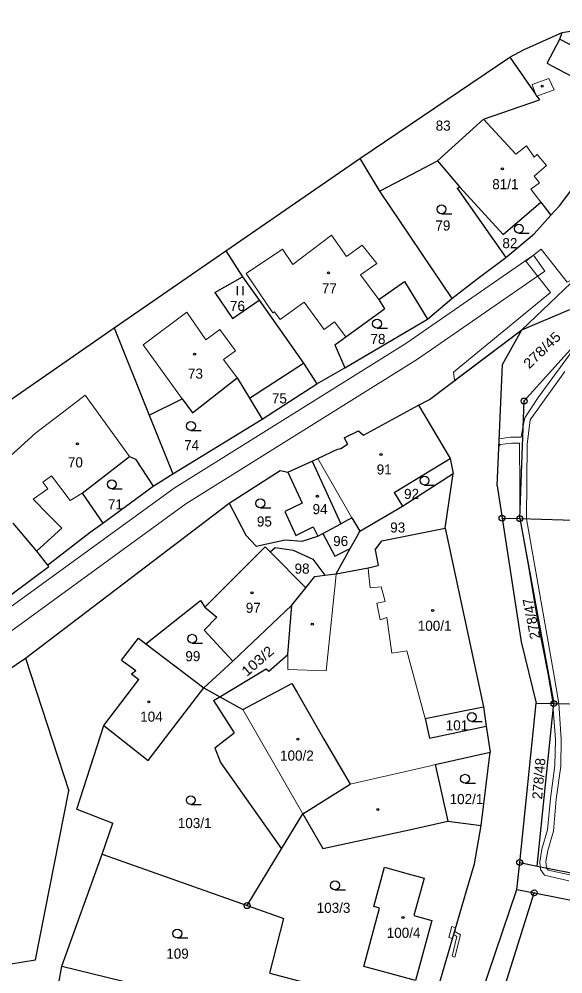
# Model space of a CAD drawing. Extents: x -633485 to -630509, y -1112692 to -1108818.
# Drawn here: x -631835.2 to -631743.5, y -1111718.1 to -1111557 of the extents above; entities that cross this region are included whole.
import ezdxf
from ezdxf.enums import TextEntityAlignment as Align

# ---------------------------------------------------------------- set-up
doc = ezdxf.new("R2010")
doc.units = 0
doc.header["$LTSCALE"] = 0.68
for name, color, linetype, lineweight in [('1', 7, 'Continuous', 25), ('13', 7, 'Continuous', 13), ('3', 7, 'Continuous', 25), ('4', 7, 'Continuous', 13), ('5', 7, 'Continuous', 25), ('8', 7, 'Continuous', 25)]:
    doc.layers.add(name, color=color, linetype=linetype, lineweight=lineweight)
doc.layers.add('2', color=7, linetype='Continuous')

msp = doc.modelspace()

# ---------------------------------------------------------------- linework, layer by layer
at = {"layer": '1'}
for p, q in [((-631743.57, -1111559.29), (-631729.66, -1111557.04)), ((-631750.09, -1111562.23), (-631743.57, -1111559.29)), ((-631743.97, -1111560.4), (-631743.57, -1111559.29)), ((-631746.12, -1111564.5), (-631743.97, -1111560.4)), ((-631743.97, -1111560.4), (-631737.55, -1111563.79)), ((-631752.41, -1111563.48), (-631750.09, -1111562.23)), ((-631777.7, -1111580.55), (-631752.41, -1111563.48)), ((-631752.41, -1111563.48), (-631748.06, -1111569.69)), ((-631746.12, -1111564.5), (-631745.34, -1111564.91)), ((-631745.34, -1111564.91), (-631739.54, -1111567.99)), ((-631748.06, -1111569.69), (-631747.93, -1111570.05)), ((-631747.93, -1111570.05), (-631747.83, -1111570.01)), ((-631747.83, -1111570.01), (-631747.38, -1111570.66)), ((-631756.86, -1111573.91), (-631747.38, -1111570.66)), ((-631764.62, -1111580.92), (-631756.86, -1111573.91)), ((-631800.32, -1111596.13), (-631777.7, -1111580.55)), ((-631777.7, -1111580.55), (-631774.39, -1111586.04)), ((-631769.01, -1111583.27), (-631764.62, -1111580.92)), ((-631764.62, -1111580.92), (-631760.86, -1111585.37)), ((-631774.39, -1111586.04), (-631769.01, -1111583.27)), ((-631774.39, -1111586.04), (-631762.2, -1111604.18)), ((-631761.3, -1111585.56), (-631760.86, -1111585.37)), ((-631761.3, -1111585.56), (-631753.08, -1111597.25)), ((-631760.86, -1111585.37), (-631753.55, -1111593.39)), ((-631744.02, -1111588.52), (-631741.6, -1111585.3)), ((-631753.55, -1111593.39), (-631747.16, -1111587.9)), ((-631747.16, -1111587.9), (-631745.47, -1111590.11)), ((-631750.36, -1111609.45), (-631728.81, -1111588.83)), ((-631745.47, -1111590.11), (-631744.02, -1111588.52)), ((-631748.32, -1111593.26), (-631745.47, -1111590.11)), ((-631753.08, -1111597.25), (-631748.32, -1111593.26)), ((-631819.16, -1111609.13), (-631800.32, -1111596.13)), ((-631800.32, -1111596.13), (-631797.47, -1111600.51)), ((-631758, -1111600.91), (-631753.08, -1111597.25)), ((-631802.15, -1111603.12), (-631797.47, -1111600.51)), ((-631797.47, -1111600.51), (-631794.69, -1111604.45)), ((-631762.2, -1111604.18), (-631758, -1111600.91)), ((-631774.51, -1111604.35), (-631770.17, -1111601.27)), ((-631770.17, -1111601.27), (-631766.3, -1111607.62)), ((-631802.15, -1111603.12), (-631799.16, -1111607.53)), ((-631799.16, -1111607.53), (-631794.69, -1111604.45)), ((-631794.69, -1111604.45), (-631787.22, -1111615.07)), ((-631774.51, -1111604.35), (-631773.54, -1111605.89)), ((-631766.3, -1111607.62), (-631762.2, -1111604.18)), ((-631780.09, -1111610.64), (-631773.54, -1111605.89)), ((-631750.36, -1111609.45), (-631742.31, -1111606)), ((-631780.24, -1111615.86), (-631766.3, -1111607.62)), ((-631848.51, -1111629.48), (-631819.16, -1111609.13)), ((-631819.16, -1111609.13), (-631813.24, -1111623.81)), ((-631781.94, -1111611.99), (-631780.09, -1111610.64)), ((-631765.95, -1111621.17), (-631750.36, -1111609.45)), ((-631753.65, -1111615.31), (-631750.36, -1111609.45)), ((-631781.94, -1111611.99), (-631780.24, -1111615.86)), ((-631796.33, -1111620.95), (-631787.22, -1111615.07)), ((-631787.22, -1111615.07), (-631784.98, -1111618.54)), ((-631754.57, -1111635.74), (-631753.65, -1111615.31)), ((-631784.98, -1111618.54), (-631780.24, -1111615.86)), ((-631805.93, -1111623.44), (-631798.41, -1111617.54)), ((-631798.41, -1111617.54), (-631796.33, -1111620.95)), ((-631794.16, -1111624.52), (-631784.98, -1111618.54)), ((-631813.24, -1111623.81), (-631807.65, -1111621.07)), ((-631807.65, -1111621.07), (-631805.93, -1111623.44)), ((-631796.33, -1111620.95), (-631794.16, -1111624.52)), ((-631777.07, -1111627.2), (-631767.81, -1111622.12)), ((-631767.81, -1111622.12), (-631765.95, -1111621.17)), ((-631767.81, -1111622.12), (-631762.49, -1111631.16)), ((-631750.72, -1111641.28), (-631750, -1111621.44)), ((-631813.24, -1111623.81), (-631809.24, -1111633.72)), ((-631809.24, -1111633.72), (-631794.16, -1111624.52)), ((-631780.33, -1111627.68), (-631777.92, -1111626.46)), ((-631777.92, -1111626.46), (-631777.07, -1111627.2)), ((-631780.33, -1111627.68), (-631779.8, -1111628.75)), ((-631784.78, -1111631.16), (-631781.47, -1111629.58)), ((-631781.47, -1111629.58), (-631780.91, -1111629.46)), ((-631780.91, -1111629.46), (-631779.8, -1111628.75)), ((-631824.55, -1111637.01), (-631816.56, -1111630.81)), ((-631816.56, -1111630.81), (-631815.55, -1111631.24)), ((-631815.55, -1111631.24), (-631812.55, -1111635.79)), ((-631789.82, -1111633.44), (-631785.75, -1111631.57)), ((-631785.75, -1111631.57), (-631784.78, -1111631.16)), ((-631785.75, -1111631.57), (-631780.9, -1111642.13)), ((-631771.89, -1111636.87), (-631762.49, -1111631.16)), ((-631762.49, -1111631.16), (-631761.94, -1111633.69)), ((-631799.75, -1111638.66), (-631791.13, -1111633.15)), ((-631791.13, -1111633.15), (-631789.82, -1111633.44)), ((-631789.82, -1111633.44), (-631787.41, -1111638.68)), ((-631812.55, -1111635.79), (-631809.24, -1111633.72)), ((-631770.53, -1111639.18), (-631761.94, -1111633.69)), ((-631763.33, -1111642.86), (-631761.94, -1111633.69)), ((-631821.06, -1111642.04), (-631812.55, -1111635.79)), ((-631754.57, -1111635.74), (-631753.72, -1111641.2)), ((-631824.55, -1111637.01), (-631821.06, -1111642.04)), ((-631771.89, -1111636.87), (-631770.53, -1111639.18)), ((-631834.1, -1111664.82), (-631799.75, -1111638.66)), ((-631799.75, -1111638.66), (-631796.95, -1111644.05)), ((-631787.41, -1111638.68), (-631790.38, -1111640.05)), ((-631777.71, -1111643.41), (-631770.53, -1111639.18)), ((-631790.38, -1111640.05), (-631788.47, -1111644.15)), ((-631780.9, -1111642.13), (-631779.75, -1111641.5)), ((-631779.75, -1111641.5), (-631779.03, -1111641.12)), ((-631779.03, -1111641.12), (-631777.71, -1111643.41)), ((-631753.72, -1111641.2), (-631750.72, -1111641.28)), ((-631753.72, -1111641.2), (-631750.49, -1111662.08)), ((-631750.72, -1111641.28), (-631744.99, -1111672.46)), ((-631750.72, -1111641.28), (-631692.44, -1111642.84)), ((-631836.24, -1111642.02), (-631832.24, -1111646.74)), ((-631823.19, -1111643.55), (-631821.06, -1111642.04)), ((-631788.47, -1111644.15), (-631785.56, -1111642.67)), ((-631785.56, -1111642.67), (-631784.78, -1111644.21)), ((-631783.95, -1111643.76), (-631780.9, -1111642.13)), ((-631773.99, -1111645.02), (-631763.33, -1111642.86)), ((-631763.33, -1111642.86), (-631756.87, -1111673)), ((-631830.36, -1111649.12), (-631823.19, -1111643.55)), ((-631796.95, -1111644.05), (-631795.16, -1111645.93)), ((-631787.43, -1111645.1), (-631784.78, -1111644.21)), ((-631784.78, -1111644.21), (-631783.95, -1111643.76)), ((-631783.95, -1111643.76), (-631781.94, -1111647.61)), ((-631779.32, -1111646.33), (-631778.22, -1111644.33)), ((-631778.22, -1111644.33), (-631777.71, -1111643.41)), ((-631803.87, -1111656.23), (-631793.68, -1111646.04)), ((-631795.16, -1111645.93), (-631790.27, -1111644.83)), ((-631793.68, -1111646.04), (-631792.85, -1111646.87)), ((-631792.85, -1111646.87), (-631792.01, -1111646.17)), ((-631792.01, -1111646.17), (-631788.92, -1111646.59)), ((-631790.27, -1111644.83), (-631787.43, -1111645.1)), ((-631781.94, -1111647.61), (-631779.32, -1111646.33)), ((-631781.67, -1111650.57), (-631779.32, -1111646.33)), ((-631775.14, -1111646.54), (-631773.99, -1111645.02)), ((-631832.24, -1111646.74), (-631830.36, -1111649.12)), ((-631792.85, -1111646.87), (-631786.79, -1111652.94)), ((-631788.92, -1111646.59), (-631785.65, -1111648.13)), ((-631775.14, -1111646.54), (-631774.63, -1111649.16)), ((-631836.57, -1111654.15), (-631830.18, -1111649.38)), ((-631830.36, -1111649.12), (-631830.18, -1111649.38)), ((-631785.65, -1111648.13), (-631783.62, -1111650.82)), ((-631776.31, -1111649.59), (-631774.63, -1111649.16)), ((-631786.79, -1111652.94), (-631785.32, -1111651.06)), ((-631785.32, -1111651.06), (-631783.62, -1111650.82)), ((-631783.62, -1111650.82), (-631781.67, -1111650.57)), ((-631781.67, -1111650.57), (-631776.31, -1111649.59)), ((-631789.19, -1111655.89), (-631786.79, -1111652.94)), ((-631813.82, -1111662.4), (-631804.57, -1111655.07)), ((-631804.57, -1111655.07), (-631803.87, -1111656.23)), ((-631799.15, -1111665.3), (-631789.19, -1111655.89)), ((-631789.83, -1111664.2), (-631789.19, -1111655.89)), ((-631803.87, -1111656.23), (-631801.82, -1111657.87)), ((-631803.97, -1111660.09), (-631801.82, -1111657.87)), ((-631803.97, -1111660.09), (-631799.15, -1111665.3)), ((-631817.91, -1111665.17), (-631815.05, -1111661.46)), ((-631815.05, -1111661.46), (-631813.82, -1111662.4)), ((-631813.82, -1111662.4), (-631804.04, -1111669.83)), ((-631750.49, -1111662.08), (-631747.99, -1111672.38)), ((-631859.21, -1111681.69), (-631834.1, -1111664.82)), ((-631834.1, -1111664.82), (-631826.76, -1111687.21)), ((-631817.91, -1111665.17), (-631815.47, -1111666.91)), ((-631804.04, -1111669.83), (-631799.15, -1111665.3)), ((-631793.06, -1111666.99), (-631789.83, -1111664.2)), ((-631816.24, -1111667.43), (-631815.47, -1111666.91)), ((-631801.33, -1111671.34), (-631793.49, -1111666.59)), ((-631793.49, -1111666.59), (-631793.06, -1111666.99)), ((-631820.9, -1111676.15), (-631814.96, -1111668.4)), ((-631816.24, -1111667.43), (-631814.96, -1111668.4)), ((-631809.75, -1111677.27), (-631804.04, -1111669.83)), ((-631804.04, -1111669.83), (-631801.33, -1111671.34)), ((-631797.46, -1111673.49), (-631789.16, -1111669.07)), ((-631789.16, -1111669.07), (-631788.29, -1111670.6)), ((-631802.37, -1111671.97), (-631801.33, -1111671.34)), ((-631802.37, -1111671.97), (-631798.91, -1111677.41)), ((-631801.33, -1111671.34), (-631797.46, -1111673.49)), ((-631788.29, -1111670.6), (-631783.79, -1111678.47)), ((-631766.69, -1111674.98), (-631756.87, -1111673)), ((-631756.87, -1111673), (-631756.41, -1111676.27)), ((-631750.74, -1111699.28), (-631747.99, -1111672.38)), ((-631747.99, -1111672.38), (-631744.99, -1111672.46)), ((-631747.8, -1111699.86), (-631744.99, -1111672.46)), ((-631744.99, -1111672.46), (-631695.61, -1111673.75)), ((-631766.69, -1111674.98), (-631765.97, -1111678.3)), ((-631825.42, -1111690.27), (-631820.9, -1111676.15)), ((-631820.9, -1111676.15), (-631813.41, -1111682.04)), ((-631765.97, -1111678.3), (-631756.41, -1111676.27)), ((-631756.41, -1111676.27), (-631755.72, -1111680.64)), ((-631813.41, -1111682.04), (-631809.75, -1111677.27)), ((-631802.16, -1111679.93), (-631798.91, -1111677.41)), ((-631783.79, -1111678.47), (-631779.36, -1111686.04)), ((-631802.16, -1111679.93), (-631801.21, -1111682.4)), ((-631765, -1111682.77), (-631755.72, -1111680.64)), ((-631757.23, -1111693.04), (-631755.72, -1111680.64)), ((-631801.21, -1111682.4), (-631790.9, -1111696.98)), ((-631765, -1111682.77), (-631762.85, -1111692.28)), ((-631787.31, -1111691.07), (-631779.36, -1111686.04)), ((-631832.42, -1111715.71), (-631826.76, -1111687.21)), ((-631825.42, -1111690.27), (-631819.36, -1111692.61)), ((-631790.9, -1111696.98), (-631787.31, -1111691.07)), ((-631787.31, -1111691.07), (-631783.94, -1111696.9)), ((-631821.17, -1111697.85), (-631819.36, -1111692.61)), ((-631769.12, -1111693.69), (-631762.85, -1111692.28)), ((-631762.85, -1111692.28), (-631757.23, -1111693.04)), ((-631783.94, -1111696.9), (-631769.12, -1111693.69)), ((-631758.38, -1111699.48), (-631757.23, -1111693.04)), ((-631827.99, -1111716.75), (-631821.17, -1111697.85)), ((-631821.17, -1111697.85), (-631796.71, -1111706.54)), ((-631796.71, -1111706.54), (-631790.9, -1111696.98)), ((-631751.2, -1111703.81), (-631750.74, -1111699.28)), ((-631750.74, -1111699.28), (-631747.8, -1111699.86)), ((-631775.33, -1111706.67), (-631773.54, -1111700.07)), ((-631773.54, -1111700.07), (-631769.55, -1111701.16)), ((-631759.7, -1111704.04), (-631758.38, -1111699.48)), ((-631747.8, -1111699.86), (-631699.26, -1111709.45)), ((-631769.55, -1111701.16), (-631766.84, -1111701.91)), ((-631766.84, -1111701.91), (-631767.17, -1111703.12)), ((-631772.51, -1111766.65), (-631751.2, -1111703.81)), ((-631767.17, -1111703.12), (-631768.57, -1111708.2)), ((-631765.44, -1111723.7), (-631759.7, -1111704.04)), ((-631751.2, -1111703.81), (-631748.3, -1111704.38)), ((-631759.55, -1111740.28), (-631748.3, -1111704.38)), ((-631748.3, -1111704.38), (-631739.51, -1111706.11)), ((-631796.71, -1111706.54), (-631790.52, -1111708.74)), ((-631777.05, -1111716.79), (-631774.37, -1111706.95)), ((-631774.37, -1111706.95), (-631775.33, -1111706.67)), ((-631792.9, -1111717.93), (-631790.52, -1111708.74)), ((-631768.57, -1111708.2), (-631765.54, -1111709.03)), ((-631765.54, -1111709.03), (-631768.33, -1111719.18)), ((-631838.71, -1111716.69), (-631832.42, -1111715.71)), ((-631828.44, -1111719.54), (-631827.99, -1111716.75)), ((-631827.99, -1111716.75), (-631812.56, -1111720.53)), ((-631773.86, -1111717.66), (-631777.05, -1111716.79)), ((-631768.33, -1111719.18), (-631773.86, -1111717.66))]:
    msp.add_line(p, q, dxfattribs=at)
for points in [[(-631750, -1111621.44), (-631740.68, -1111611.08), (-631713.85, -1111595.51)], [(-631792.9, -1111717.93), (-631765.89, -1111725.06), (-631765.44, -1111723.7)]]:
    msp.add_lwpolyline(points, dxfattribs=at)
at = {"layer": '13'}
for points in [[(-631761.74, -1111618.01), (-631750.36, -1111609.45), (-631740.93, -1111600.43), (-631742.73, -1111601.38), (-631747.13, -1111595.83), (-631748.39, -1111596.83), (-631749.72, -1111597.88), (-631745.53, -1111603.16), (-631761.93, -1111616.6)], [(-631762.72, -1111711.9), (-631762.05, -1111712.09), (-631761.85, -1111711.42), (-631761.71, -1111710.93), (-631761.51, -1111710.26), (-631762.19, -1111710.06)], [(-631761.71, -1111710.93), (-631761.85, -1111711.42), (-631761.32, -1111711.72), (-631762.16, -1111715.08), (-631761.68, -1111715.21), (-631760.74, -1111711.46)]]:
    msp.add_lwpolyline(points, close=True, dxfattribs=at)
for points in [[(-631935.9, -1111727.56), (-631914.51, -1111711.36), (-631885.8, -1111692.49), (-631844.62, -1111666.09), (-631807.03, -1111638.81), (-631767.97, -1111614.41), (-631746.51, -1111599.55), (-631748.39, -1111596.83), (-631769.96, -1111611.77), (-631809.01, -1111636.17), (-631846.6, -1111663.43), (-631887.58, -1111689.71), (-631916.51, -1111708.73), (-631937.96, -1111724.98)], [(-631740.85, -1111611.6), (-631743.93, -1111615.77), (-631747.64, -1111620.84), (-631749.89, -1111624.26), (-631750.15, -1111625.65), (-631750.5, -1111627.53), (-631752.31, -1111627.57), (-631754.21, -1111627.8), (-631754.27, -1111629.1), (-631754.04, -1111628.79), (-631752.15, -1111628.57), (-631750.79, -1111628.54), (-631750.73, -1111635.97), (-631750.72, -1111641.28), (-631749.24, -1111649.32), (-631747.69, -1111658.79), (-631746, -1111667.36), (-631745.18, -1111672.26), (-631745.59, -1111672.39), (-631745.57, -1111672.44), (-631745.44, -1111672.87), (-631745.13, -1111672.77), (-631745.09, -1111673.4), (-631744.73, -1111678.51), (-631744.81, -1111682.93), (-631745.57, -1111688.46), (-631746.04, -1111693.78), (-631746.99, -1111697), (-631747.37, -1111699.13), (-631747.27, -1111699.97), (-631747.21, -1111700.44), (-631746.57, -1111701.43), (-631742.46, -1111702.35)], [(-631742.26, -1111701.37), (-631745.95, -1111700.55), (-631746.21, -1111700.17), (-631746.36, -1111699.16), (-631746.01, -1111697.22), (-631745.06, -1111693.96), (-631744.57, -1111688.58), (-631743.81, -1111683.01), (-631743.73, -1111678.49), (-631744.13, -1111672.48), (-631745.02, -1111667.18), (-631749.57, -1111641.31), (-631749.47, -1111628.8), (-631748.95, -1111624.64), (-631743.11, -1111616.48)]]:
    msp.add_lwpolyline(points, dxfattribs=at)
at = {"layer": '3'}
for p, q in [((-631763.933, -1111589.87), (-631762.183, -1111589.87)), ((-631750.883, -1111593.13), (-631749.133, -1111593.13)), ((-631798.361, -1111603.58), (-631798.361, -1111602.08)), ((-631797.36, -1111603.58), (-631797.36, -1111602.08)), ((-631774.793, -1111609.16), (-631773.043, -1111609.16)), ((-631806.193, -1111626.42), (-631804.443, -1111626.42)), ((-631819.533, -1111636.23), (-631817.783, -1111636.23)), ((-631766.793, -1111635.61), (-631765.043, -1111635.61)), ((-631794.483, -1111639.46), (-631792.733, -1111639.46)), ((-631805.983, -1111662.29), (-631804.233, -1111662.29)), ((-631758.823, -1111675.48), (-631757.073, -1111675.48)), ((-631759.953, -1111685.9), (-631758.203, -1111685.9)), ((-631806.213, -1111689.51), (-631804.463, -1111689.51)), ((-631781.893, -1111703.87), (-631780.143, -1111703.87)), ((-631808.483, -1111712), (-631806.733, -1111712))]:
    msp.add_line(p, q, dxfattribs=at)
for centre in [(-631763.9329, -1111589.1198), (-631750.8829, -1111592.3798), (-631774.7929, -1111608.4098), (-631806.1929, -1111625.6698), (-631819.5329, -1111635.4798), (-631766.7929, -1111634.8598), (-631794.4829, -1111638.7098), (-631805.9829, -1111661.5398), (-631758.8229, -1111674.7298), (-631759.9529, -1111685.1498), (-631806.2129, -1111688.7598), (-631781.8929, -1111703.1198), (-631808.4829, -1111711.2498)]:
    msp.add_circle(centre, 0.75, dxfattribs=at)
at = {"layer": '4'}
for p, q in [((-631748.65, -1111568.07), (-631745.83, -1111567.07)), ((-631745.83, -1111567.07), (-631744.95, -1111568.96)), ((-631748.65, -1111568.07), (-631748.06, -1111569.69)), ((-631747.83, -1111570.01), (-631744.95, -1111568.96)), ((-631756.86, -1111573.91), (-631751.37, -1111579.84)), ((-631751.37, -1111579.84), (-631749.61, -1111578.41)), ((-631749.61, -1111578.41), (-631748.29, -1111580.3)), ((-631748.29, -1111580.3), (-631747.77, -1111579.87)), ((-631747.77, -1111579.87), (-631746.2, -1111581.74)), ((-631748.32, -1111583.53), (-631746.2, -1111581.74)), ((-631748.32, -1111583.53), (-631747.38, -1111584.66)), ((-631748.88, -1111585.74), (-631747.38, -1111584.66)), ((-631748.88, -1111585.74), (-631747.16, -1111587.9)), ((-631789.02, -1111598.4), (-631782.5, -1111593.5)), ((-631782.5, -1111593.5), (-631779.94, -1111597.08)), ((-631796.87, -1111599.96), (-631790.72, -1111595.85)), ((-631790.72, -1111595.85), (-631789.02, -1111598.4)), ((-631779.94, -1111597.08), (-631777.3, -1111595.17)), ((-631777.3, -1111595.17), (-631774.85, -1111598.27)), ((-631777.61, -1111600.18), (-631774.85, -1111598.27)), ((-631796.87, -1111599.96), (-631792.36, -1111606.6)), ((-631777.61, -1111600.18), (-631774.51, -1111604.35)), ((-631791.14, -1111607.7), (-631787.09, -1111604.76)), ((-631787.09, -1111604.76), (-631783.74, -1111609.38)), ((-631814.24, -1111611.96), (-631806.89, -1111606.44)), ((-631806.89, -1111606.44), (-631803.66, -1111611.12)), ((-631792.36, -1111606.6), (-631792.09, -1111606.4)), ((-631792.09, -1111606.4), (-631791.14, -1111607.7)), ((-631783.74, -1111609.38), (-631781.95, -1111608.08)), ((-631781.95, -1111608.08), (-631780.09, -1111610.64)), ((-631803.66, -1111611.12), (-631801.29, -1111609.4)), ((-631801.29, -1111609.4), (-631798.7, -1111612.98)), ((-631814.24, -1111611.96), (-631807.65, -1111621.07)), ((-631800.72, -1111614.44), (-631798.7, -1111612.98)), ((-631800.72, -1111614.44), (-631798.41, -1111617.54)), ((-631826.02, -1111621.98), (-631824.03, -1111620.46)), ((-631824.03, -1111620.46), (-631816.56, -1111630.81)), ((-631832.41, -1111626.84), (-631826.02, -1111621.98)), ((-631838.52, -1111632.36), (-631832.41, -1111626.84)), ((-631784.78, -1111631.16), (-631779.03, -1111641.12)), ((-631831.14, -1111635.11), (-631829.7, -1111634.04)), ((-631829.7, -1111634.04), (-631826.58, -1111638.25)), ((-631832.79, -1111637.99), (-631830.31, -1111636.23)), ((-631831.14, -1111635.11), (-631830.31, -1111636.23)), ((-631832.79, -1111637.99), (-631830.15, -1111640.69)), ((-631826.58, -1111638.25), (-631824.55, -1111637.01)), ((-631830.15, -1111640.69), (-631827.96, -1111642.91)), ((-631832.24, -1111646.74), (-631827.96, -1111642.91)), ((-631781.74, -1111651.28), (-631781.67, -1111650.57)), ((-631776.24, -1111650.29), (-631776.31, -1111649.59)), ((-631776.24, -1111650.29), (-631775.97, -1111652.97)), ((-631783.38, -1111666.96), (-631781.74, -1111651.28)), ((-631775.97, -1111652.97), (-631774.11, -1111652.79)), ((-631774.11, -1111652.79), (-631773.43, -1111655.25)), ((-631774.83, -1111655.51), (-631773.43, -1111655.25)), ((-631774.83, -1111655.51), (-631774.3, -1111658.33)), ((-631774.3, -1111658.33), (-631773.14, -1111657.96)), ((-631773.14, -1111657.96), (-631772.29, -1111663.99)), ((-631772.29, -1111663.99), (-631769.8, -1111663.6)), ((-631769.8, -1111663.6), (-631766.69, -1111674.98)), ((-631789.84, -1111666.74), (-631789.83, -1111664.2)), ((-631789.84, -1111666.74), (-631783.38, -1111666.96)), ((-631797.46, -1111673.49), (-631787.31, -1111691.07)), ((-631779.36, -1111686.04), (-631765.8, -1111682.95)), ((-631765.8, -1111682.95), (-631765, -1111682.77))]:
    msp.add_line(p, q, dxfattribs=at)
at = {"layer": '5'}
for centre in [(-631746.9468, -1111568.3592), (-631753.6668, -1111582.2892), (-631782.9968, -1111599.8292), (-631805.5668, -1111613.5492), (-631825.3368, -1111628.6692), (-631774.1368, -1111630.4692), (-631784.8668, -1111637.5092), (-631795.8868, -1111653.7992), (-631765.4268, -1111656.7792), (-631785.7168, -1111659.0692), (-631813.2868, -1111672.1592), (-631788.1568, -1111678.4792), (-631774.6668, -1111690.3192), (-631770.4268, -1111708.5292)]:
    msp.add_circle(centre, 0.175, dxfattribs=at)
at = {"layer": '8'}
for centre, radius in [((-631750, -1111621.4399), 0.5), ((-631750, -1111621.4399), 0.0303), ((-631753.72, -1111641.1999), 0.5), ((-631753.72, -1111641.1999), 0.0303), ((-631750.72, -1111641.2799), 0.5), ((-631750.72, -1111641.2799), 0.0303), ((-631744.99, -1111672.4599), 0.5), ((-631744.99, -1111672.4599), 0.0303), ((-631750.74, -1111699.2799), 0.5), ((-631750.74, -1111699.2799), 0.0303), ((-631748.3, -1111704.3799), 0.5), ((-631748.3, -1111704.3799), 0.0303), ((-631796.71, -1111706.5399), 0.5), ((-631796.71, -1111706.5399), 0.0303)]:
    msp.add_circle(centre, radius, dxfattribs=at)

# ---------------------------------------------------------------- texts
at = {"layer": '2'}
for s, p in [('83', (-631764.91, -1111575.855)), ('81/1', (-631755.37, -1111585.725)), ('79', (-631764.96, -1111592.695)), ('82', (-631753.66, -1111595.675)), ('77', (-631784.11, -1111603.305)), ('76', (-631799.61, -1111606.255)), ('78', (-631775.91, -1111611.835)), ('73', (-631806.69, -1111617.675)), ('75', (-631792.54, -1111621.855)), ('74', (-631807.33, -1111629.735)), ('70', (-631826.94, -1111632.635)), ('91', (-631774.86, -1111633.835)), ('92', (-631770.24, -1111637.955)), ('71', (-631820.19, -1111639.715)), ('94', (-631785.67, -1111640.525)), ('95', (-631795.06, -1111642.605)), ('93', (-631772.58, -1111643.625)), ('96', (-631782.2, -1111645.905)), ('98', (-631788.71, -1111650.555)), ('97', (-631796.94, -1111657.165)), ('100/1', (-631767.93, -1111660.195)), ('99', (-631807.13, -1111665.325)), ('104', (-631814.75, -1111675.525)), ('101', (-631763.22, -1111676.985)), ('100/2', (-631791.16, -1111682.085)), ('102/1', (-631762.56, -1111689.425)), ('103/1', (-631808.4, -1111693.465)), ('103/3', (-631784.98, -1111707.765)), ('100/4', (-631773.17, -1111711.975)), ('109', (-631810.35, -1111715.485))]:
    msp.add_text(s, height=1.7, dxfattribs=at).set_placement(p)
at = {"layer": '2', "width": 1.1}
msp.add_text('278/45', height=1.7, rotation=44, dxfattribs=at).set_placement((-631746.3875, -1111613.4613), align=Align.CENTER)
at = {"layer": '2'}
for s, rotation, p in [('278/47', 101, (-631747.9285, -1111658.0057)), ('278/48', 85, (-631746.6726, -1111685.1991))]:
    msp.add_text(s, height=1.7, rotation=rotation, dxfattribs=at).set_placement(p, align=Align.CENTER)
at = {"layer": '2', "width": 1.1}
msp.add_text('103/2', height=1.7, rotation=41, dxfattribs=at).set_placement((-631796.751, -1111667.99))

doc.saveas('drawing.dxf')
